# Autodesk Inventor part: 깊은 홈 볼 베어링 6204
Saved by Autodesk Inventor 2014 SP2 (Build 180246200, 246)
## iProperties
Created: 2024-04
Part Number: 깊은 홈 볼 베어링 6204
Material: Generic
Document SubType Name: Modeling
Designer: Administrator
Density: 1 g/cm^3
Appearance: Default
Author: Administrator
Author: jhkim
Description: 깊은 그루브 볼 베어링
Creation Date: 2024-04-08
Sending System: Autodesk Inventor 2025
Preprocessor: ST-DEVELOPER v20
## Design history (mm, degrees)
node "깊은 홈 볼 베어링 62041"
body "Solid1"
node "Solid1_1"
node "Solid1_2"
node "Solid1_3"
node "Solid1_4"
node "Solid1_5"
node "Solid1_6"
node "Solid1_7"
node "Solid1_8"
node "기준1"
node "기준2"
node "기준3"
node "기준4"
node "기준5"
node "기준6"
node "기준7"
node "기준8"
node "기준9"
